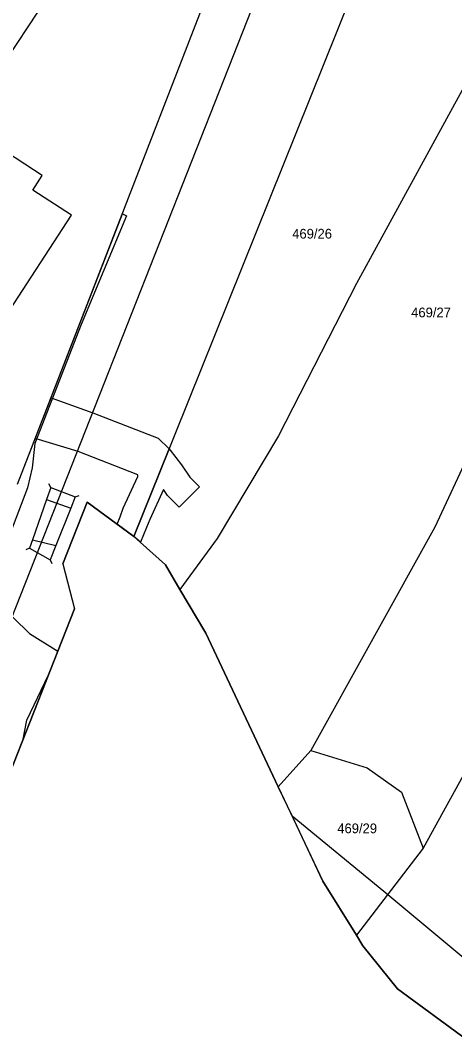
# Model space of a CAD drawing. Extents: x -755359 to -754474, y -1162585 to -1161655.
# Drawn here: x -754728 to -754652.1, y -1161962 to -1161783.9 of the extents above; entities that cross this region are included whole.
import ezdxf

# ---------------------------------------------------------------- set-up
doc = ezdxf.new("R2010")
doc.units = 0
for name, color, linetype in [('Vrstva 1', 7, 'Continuous'), ('Vrstva 11', 7, 'Continuous'), ('Vrstva 12', 7, 'Continuous'), ('Vrstva 13', 7, 'Continuous'), ('Vrstva 2', 7, 'Continuous'), ('Vrstva 4', 7, 'Continuous'), ('Vrstva 6', 7, 'Continuous')]:
    doc.layers.add(name, color=color, linetype=linetype)

msp = doc.modelspace()

# ---------------------------------------------------------------- linework, layer by layer
at = {"layer": 'Vrstva 1'}
for p, q in [((-754728.5, -1161864.92), (-754687.63, -1161759.49)), ((-754665.97, -1161769.03), (-754708.18, -1161874.05)), ((-754643.13, -1161782.03), (-754669.27, -1161829.84)), ((-754724.19, -1161811.01), (-754763.46, -1161785.44)), ((-754725.85, -1161813.54), (-754724.19, -1161811.01)), ((-754719.1, -1161817.94), (-754725.85, -1161813.54)), ((-754730.68, -1161835.75), (-754719.1, -1161817.94)), ((-754633.36, -1161824.71), (-754655.58, -1161872.43)), ((-754669.27, -1161829.84), (-754682.9, -1161856.46)), ((-754682.9, -1161856.46), (-754693.64, -1161874.43)), ((-754720.58, -1161878.83), (-754716.32, -1161868.1)), ((-754716.32, -1161868.1), (-754708.18, -1161874.05)), ((-754655.58, -1161872.43), (-754677.24, -1161911.45)), ((-754708.18, -1161874.05), (-754702.66, -1161879.01)), ((-754693.64, -1161874.43), (-754700.13, -1161883.31)), ((-754720.58, -1161878.83), (-754718.58, -1161886.73)), ((-754702.66, -1161879.01), (-754700.13, -1161883.31)), ((-754700.13, -1161883.31), (-754695.62, -1161890.99)), ((-754747.41, -1161959.83), (-754718.58, -1161886.73)), ((-754695.62, -1161890.99), (-754682.93, -1161917.84)), ((-754643, -1161901.95), (-754657.61, -1161928.54)), ((-754677.24, -1161911.45), (-754682.93, -1161917.84)), ((-754677.24, -1161911.45), (-754667.41, -1161914.5)), ((-754667.41, -1161914.5), (-754661.4, -1161918.76)), ((-754682.93, -1161917.84), (-754675.16, -1161934.28)), ((-754661.4, -1161918.76), (-754657.61, -1161928.54)), ((-754657.61, -1161928.54), (-754669.27, -1161943.74)), ((-754675.16, -1161934.28), (-754669.27, -1161943.74)), ((-754669.27, -1161943.74), (-754668.12, -1161945.6)), ((-754668.12, -1161945.6), (-754662.1, -1161953.11)), ((-754662.1, -1161953.11), (-754649.99, -1161962))]:
    msp.add_line(p, q, dxfattribs=at)
at = {"layer": 'Vrstva 11'}
for p, q in [((-754716.32, -1161868.1), (-754720.58, -1161878.83)), ((-754708.18, -1161874.05), (-754716.32, -1161868.1)), ((-754702.66, -1161879.01), (-754708.18, -1161874.05)), ((-754720.58, -1161878.83), (-754718.58, -1161886.73)), ((-754700.13, -1161883.31), (-754702.66, -1161879.01)), ((-754735.08, -1161882.66), (-754726.41, -1161891)), ((-754695.62, -1161890.99), (-754700.13, -1161883.31)), ((-754718.58, -1161886.73), (-754721.5, -1161894.13)), ((-754726.41, -1161891), (-754721.5, -1161894.13)), ((-754682.93, -1161917.84), (-754695.62, -1161890.99)), ((-754721.5, -1161894.13), (-754747.41, -1161959.83)), ((-754680.53, -1161922.91), (-754682.93, -1161917.84)), ((-754675.16, -1161934.28), (-754680.53, -1161922.91)), ((-754680.53, -1161922.91), (-754664.48, -1161936.05)), ((-754669.27, -1161943.74), (-754675.16, -1161934.28)), ((-754664.48, -1161936.05), (-754663.8, -1161936.61)), ((-754663.8, -1161936.61), (-754639.14, -1161957.17)), ((-754668.12, -1161945.6), (-754669.27, -1161943.74)), ((-754662.1, -1161953.11), (-754668.12, -1161945.6)), ((-754649.99, -1161962), (-754662.1, -1161953.11))]:
    msp.add_line(p, q, dxfattribs=at)
at = {"layer": 'Vrstva 12'}
for p, q in [((-754724.19, -1161811.01), (-754763.46, -1161785.44)), ((-754725.85, -1161813.54), (-754724.19, -1161811.01)), ((-754719.1, -1161817.94), (-754725.85, -1161813.54)), ((-754730.68, -1161835.75), (-754719.1, -1161817.94))]:
    msp.add_line(p, q, dxfattribs=at)
at = {"layer": 'Vrstva 13'}
for p, q in [((-754728.5, -1161864.92), (-754710.18, -1161817.66)), ((-754709.46, -1161818.01), (-754717.42, -1161837.05)), ((-754710.18, -1161817.66), (-754709.46, -1161818.01)), ((-754717.42, -1161837.05), (-754725.52, -1161857.81)), ((-754725.42, -1161856.97), (-754722.65, -1161849.82)), ((-754722.65, -1161849.82), (-754715.34, -1161852.48)), ((-754715.34, -1161852.48), (-754703.95, -1161856.87)), ((-754717.93, -1161859.23), (-754725.42, -1161856.97)), ((-754703.95, -1161856.87), (-754702.03, -1161858.75)), ((-754725.52, -1161857.81), (-754725.94, -1161862.08)), ((-754707.46, -1161863.28), (-754717.93, -1161859.23)), ((-754702.03, -1161858.75), (-754708.18, -1161874.05)), ((-754708.18, -1161874.05), (-754702.03, -1161858.75)), ((-754702.03, -1161858.75), (-754701.81, -1161858.97)), ((-754701.81, -1161858.97), (-754699.88, -1161861.55)), ((-754725.94, -1161862.08), (-754726.76, -1161865.59)), ((-754699.88, -1161861.55), (-754698.42, -1161863.72)), ((-754710.03, -1161869.14), (-754707.5, -1161863.6)), ((-754707.5, -1161863.6), (-754707.46, -1161863.28)), ((-754698.42, -1161863.72), (-754696.72, -1161865.42)), ((-754726.76, -1161865.59), (-754736.9, -1161891.63)), ((-754703.02, -1161865.84), (-754705.41, -1161871.08)), ((-754702.3, -1161866.92), (-754703.02, -1161865.84)), ((-754696.72, -1161865.42), (-754700.26, -1161868.96)), ((-754700.26, -1161868.96), (-754702.3, -1161866.92)), ((-754710.6, -1161870.65), (-754710.03, -1161869.14)), ((-754711.12, -1161871.9), (-754710.6, -1161870.65)), ((-754708.18, -1161874.05), (-754711.12, -1161871.9)), ((-754705.41, -1161871.08), (-754705.96, -1161872.49)), ((-754705.96, -1161872.49), (-754707.02, -1161875.09)), ((-754707.02, -1161875.09), (-754708.18, -1161874.05)), ((-754723.12, -1161898.24), (-754727.55, -1161909.47)), ((-754726.88, -1161906.17), (-754723.12, -1161898.24)), ((-754727.55, -1161909.47), (-754726.88, -1161906.17))]:
    msp.add_line(p, q, dxfattribs=at)
at = {"layer": 'Vrstva 4'}
for p, q in [((-754679.82, -1161714.24), (-754733.53, -1161795.26)), ((-754722.7, -1161865.5), (-754723.43, -1161867.58)), ((-754722.7, -1161865.5), (-754723.023, -1161864.871)), ((-754722.7, -1161865.5), (-754718.42, -1161867.12)), ((-754723.43, -1161867.58), (-754725.93, -1161874.67)), ((-754723.43, -1161867.58), (-754719.23, -1161869.15)), ((-754718.42, -1161867.12), (-754719.23, -1161869.15)), ((-754718.42, -1161867.12), (-754717.739, -1161866.931)), ((-754719.23, -1161869.15), (-754721.83, -1161875.65)), ((-754725.93, -1161874.67), (-754726.44, -1161876.09)), ((-754725.93, -1161874.67), (-754721.83, -1161875.65)), ((-754726.44, -1161876.09), (-754727.08, -1161876.391)), ((-754726.44, -1161876.09), (-754722.83, -1161878.17)), ((-754721.83, -1161875.65), (-754722.83, -1161878.17)), ((-754722.83, -1161878.17), (-754722.548, -1161878.818))]:
    msp.add_line(p, q, dxfattribs=at)
at = {"layer": 'Vrstva 6'}
msp.add_line((-754684.25, -1161773.32), (-754736, -1161904.52), dxfattribs=at)

# ---------------------------------------------------------------- texts
at = {"layer": 'Vrstva 2'}
for s, p in [('469/26', (-754680.493, -1161822.01)), ('469/27', (-754659.693, -1161835.77)), ('469/29', (-754672.613, -1161925.93))]:
    msp.add_text(s, height=1.7, dxfattribs=at).set_placement(p)

doc.saveas('drawing.dxf')
